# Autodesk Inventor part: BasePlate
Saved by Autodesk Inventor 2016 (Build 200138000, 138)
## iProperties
Created: 2015-11
Part Number: BasePlate
Material: Generic
Document SubType Name: Modeling
Designer: John
Density: 1 g/cm^3
Appearance: Default
Author: John
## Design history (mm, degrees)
feature "SOLID1"
body "Solid1"
